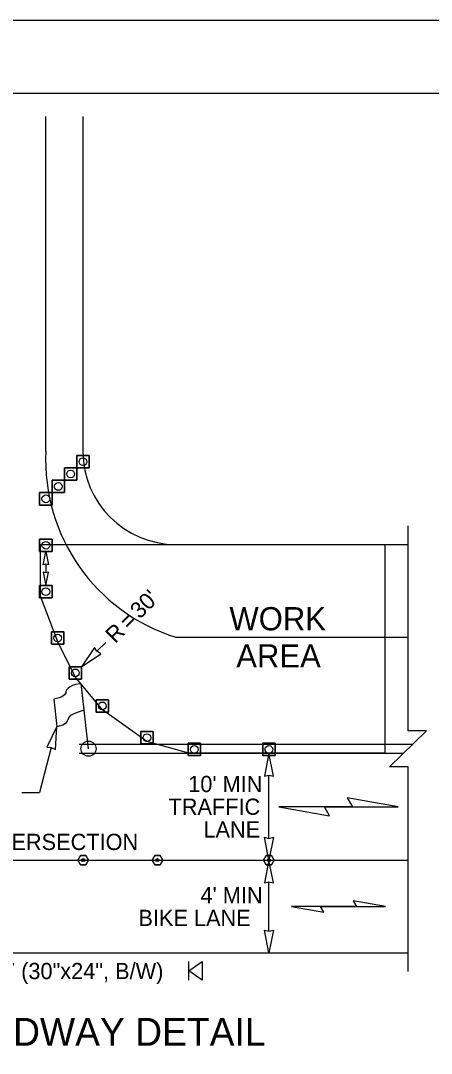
# Model space of a CAD drawing. Extents: x 99998.9 to 100095.7, y 99995 to 100010.7.
# Drawn here: x 100068.607 to 100070.375, y 100006.238 to 100010.687 of the extents above; entities that cross this region are included whole.
import ezdxf

# ---------------------------------------------------------------- set-up
doc = ezdxf.new("R2010")
doc.units = 0
for name, color, linetype in [('RD_ED_ShoulderPavedEdge', 7, 'Continuous'), ('RD_MK_LineDblYellowCenter', 7, 'Continuous'), ('RD_MK_LineEdgeWhite', 7, 'Continuous'), ('SH_DE_DetailHeading2Text', 7, 'Continuous'), ('SH_GI_PlotLimits', 7, 'Continuous'), ('SH_GI_SheetBorder', 7, 'Continuous'), ('TR_WZ_FlaggingStation', 7, 'Continuous'), ('TR_WZ_PortableSignMountBlk-Wht', 7, 'Continuous'), ('TR_WZ_TrafficCone', 7, 'Continuous'), ('TR_WZ_TubularMarker', 7, 'Continuous'), ('TR_WZ_WorkAreaLabel', 7, 'Continuous'), ('TR_WZ_WorkZoneDetails', 7, 'Continuous'), ('TR_WZ_WorkZoneTextCurrent', 7, 'Continuous')]:
    doc.layers.add(name, color=color, linetype=linetype)

msp = doc.modelspace()

# ---------------------------------------------------------------- linework, layer by layer
at = {"layer": 'RD_ED_ShoulderPavedEdge'}
for p, q in [((100069.275, 100008.4305), (100070.275, 100008.4305)), ((100065.475, 100006.6704), (100070.275, 100006.6704))]:
    msp.add_line(p, q, dxfattribs=at)
msp.add_lwpolyline([(100068.875, 100010.275), (100068.875, 100008.8304)], dxfattribs=at)
msp.add_arc((100069.275, 100008.8304), 0.4, 180, 270, dxfattribs=at)
at = {"layer": 'RD_MK_LineDblYellowCenter'}
for p, q in [((100068.8588, 100007.5704), (100070.2957, 100007.5704)), ((100068.8588, 100007.5305), (100070.2543, 100007.5305))]:
    msp.add_line(p, q, dxfattribs=at)
at = {"layer": 'RD_MK_LineEdgeWhite'}
for p, q in [((100068.715, 100008.8304), (100068.715, 100010.275)), ((100069.275, 100008.0305), (100070.275, 100008.0305)), ((100065.475, 100007.0704), (100070.275, 100007.0704))]:
    msp.add_line(p, q, dxfattribs=at)
msp.add_arc((100069.5142, 100008.7939), 0.8, 177.3788, 252.6052, dxfattribs=at)
at = {"layer": 'SH_GI_PlotLimits'}
msp.add_lwpolyline([(100059.0625, 99999.6875), (100076.0625, 99999.6875), (100076.0625, 100010.6875), (100059.0625, 100010.6875)], close=True, dxfattribs=at)
at = {"layer": 'SH_GI_SheetBorder'}
msp.add_line((100060, 100010.375), (100075.75, 100010.375), dxfattribs=at)
at = {"layer": 'TR_WZ_FlaggingStation'}
for p, q in [((100068.8797, 100007.7174), (100068.8667, 100007.8317)), ((100068.8988, 100007.5504), (100068.8667, 100007.8314)), ((100068.7487, 100007.7639), (100068.762, 100007.6467)), ((100068.8797, 100007.7174), (100068.8797, 100007.7174))]:
    msp.add_line(p, q, dxfattribs=at)
for points in [[(100068.8667, 100007.8317), (100068.8609, 100007.8304), (100068.8431, 100007.827), (100068.8293, 100007.8228), (100068.8196, 100007.8167), (100068.8111, 100007.812), (100068.8054, 100007.8052), (100068.8012, 100007.7973), (100068.8006, 100007.7912), (100068.7953, 100007.7819), (100068.7845, 100007.7745), (100068.7721, 100007.7693), (100068.7487, 100007.7639)], [(100068.762, 100007.6467), (100068.7702, 100007.6481), (100068.7879, 100007.6528), (100068.8035, 100007.6633), (100068.81, 100007.6738), (100068.814, 100007.6841), (100068.823, 100007.695), (100068.834, 100007.7012), (100068.8514, 100007.7083), (100068.8797, 100007.7174)]]:
    msp.add_lwpolyline(points, dxfattribs=at)
msp.add_circle((100068.8988, 100007.5504), 0.0325, dxfattribs=at)
at = {"layer": 'TR_WZ_PortableSignMountBlk-Wht'}
msp.add_line((100069.331, 100006.5536), (100069.331, 100006.6336), dxfattribs=at)
msp.add_lwpolyline([(100069.331, 100006.5935), (100069.3885, 100006.6336), (100069.3885, 100006.5536)], close=True, dxfattribs=at)
at = {"layer": 'TR_WZ_TrafficCone'}
for points in [[(100068.8483, 100008.8138), (100068.8483, 100008.7605), (100068.9016, 100008.7605), (100068.9016, 100008.8138), (100068.8483, 100008.8138)], [(100068.9016, 100008.8138), (100068.9016, 100008.7605), (100068.8483, 100008.7605), (100068.8483, 100008.8138), (100068.9016, 100008.8138)], [(100068.795, 100008.7605), (100068.795, 100008.7071), (100068.8483, 100008.7071), (100068.8483, 100008.7605), (100068.795, 100008.7605)], [(100068.8483, 100008.7605), (100068.8483, 100008.7071), (100068.795, 100008.7071), (100068.795, 100008.7605), (100068.8483, 100008.7605)], [(100068.7416, 100008.7071), (100068.7416, 100008.6538), (100068.795, 100008.6538), (100068.795, 100008.7071), (100068.7416, 100008.7071)], [(100068.795, 100008.7071), (100068.795, 100008.6538), (100068.7416, 100008.6538), (100068.7416, 100008.7071), (100068.795, 100008.7071)], [(100068.6883, 100008.6538), (100068.7416, 100008.6538), (100068.7416, 100008.6005), (100068.6883, 100008.6005), (100068.6883, 100008.6538)], [(100068.6883, 100008.6005), (100068.7416, 100008.6005), (100068.7416, 100008.6538), (100068.6883, 100008.6538), (100068.6883, 100008.6005)], [(100068.6883, 100008.4538), (100068.7416, 100008.4538), (100068.7416, 100008.4005), (100068.6883, 100008.4005), (100068.6883, 100008.4538)], [(100068.6883, 100008.4005), (100068.7416, 100008.4005), (100068.7416, 100008.4538), (100068.6883, 100008.4538), (100068.6883, 100008.4005)], [(100068.6883, 100008.2538), (100068.7416, 100008.2538), (100068.7416, 100008.2005), (100068.6883, 100008.2005), (100068.6883, 100008.2538)], [(100068.6883, 100008.2005), (100068.7416, 100008.2005), (100068.7416, 100008.2538), (100068.6883, 100008.2538), (100068.6883, 100008.2005)], [(100068.7393, 100008.0538), (100068.7927, 100008.0538), (100068.7927, 100008.0005), (100068.7393, 100008.0005), (100068.7393, 100008.0538)], [(100068.7393, 100008.0005), (100068.7927, 100008.0005), (100068.7927, 100008.0538), (100068.7393, 100008.0538), (100068.7393, 100008.0005)], [(100068.815, 100007.9038), (100068.8683, 100007.9038), (100068.8683, 100007.8505), (100068.815, 100007.8505), (100068.815, 100007.9038)], [(100068.815, 100007.8505), (100068.8683, 100007.8505), (100068.8683, 100007.9038), (100068.815, 100007.9038), (100068.815, 100007.8505)], [(100068.9319, 100007.7615), (100068.9853, 100007.7615), (100068.9853, 100007.7082), (100068.9319, 100007.7082), (100068.9319, 100007.7615)], [(100068.9319, 100007.7082), (100068.9853, 100007.7082), (100068.9853, 100007.7615), (100068.9319, 100007.7615), (100068.9319, 100007.7082)], [(100069.1236, 100007.6247), (100069.177, 100007.6247), (100069.177, 100007.5714), (100069.1236, 100007.5714), (100069.1236, 100007.6247)], [(100069.1236, 100007.5714), (100069.177, 100007.5714), (100069.177, 100007.6247), (100069.1236, 100007.6247), (100069.1236, 100007.5714)], [(100069.3276, 100007.5738), (100069.381, 100007.5738), (100069.381, 100007.5205), (100069.3276, 100007.5205), (100069.3276, 100007.5738)], [(100069.3276, 100007.5205), (100069.381, 100007.5205), (100069.381, 100007.5738), (100069.3276, 100007.5738), (100069.3276, 100007.5205)], [(100069.649, 100007.5738), (100069.7024, 100007.5738), (100069.7024, 100007.5205), (100069.649, 100007.5205), (100069.649, 100007.5738)], [(100069.649, 100007.5205), (100069.7024, 100007.5205), (100069.7024, 100007.5738), (100069.649, 100007.5738), (100069.649, 100007.5205)]]:
    msp.add_lwpolyline(points, dxfattribs=at)
for centre in [(100068.875, 100008.7871), (100068.8216, 100008.7338), (100068.7683, 100008.6805), (100068.715, 100008.6271), (100068.715, 100008.4271), (100068.715, 100008.2271), (100068.766, 100008.0271), (100068.8417, 100007.8771), (100068.9586, 100007.7349), (100069.1503, 100007.598), (100069.3543, 100007.5471), (100069.6757, 100007.5471)]:
    msp.add_circle(centre, 0.0167, dxfattribs=at)
at = {"layer": 'TR_WZ_TubularMarker'}
for points in [[(100068.8526, 100007.0704), (100068.8641, 100007.0904), (100068.8872, 100007.0904), (100068.8988, 100007.0704), (100068.8872, 100007.0504), (100068.8641, 100007.0504)], [(100069.1726, 100007.0704), (100069.1841, 100007.0904), (100069.2072, 100007.0904), (100069.2188, 100007.0704), (100069.2072, 100007.0504), (100069.1841, 100007.0504)], [(100069.6526, 100007.0704), (100069.6641, 100007.0904), (100069.6872, 100007.0904), (100069.6988, 100007.0704), (100069.6872, 100007.0504), (100069.6641, 100007.0504)]]:
    msp.add_lwpolyline(points, close=True, dxfattribs=at)
for points in [[(100068.8641, 100007.0504), (100068.8872, 100007.0504), (100068.8988, 100007.0704), (100068.8872, 100007.0904), (100068.8641, 100007.0904), (100068.8526, 100007.0704), (100068.8641, 100007.0504)], [(100069.1841, 100007.0504), (100069.2072, 100007.0504), (100069.2188, 100007.0704), (100069.2072, 100007.0904), (100069.1841, 100007.0904), (100069.1726, 100007.0704), (100069.1841, 100007.0504)], [(100069.6641, 100007.0504), (100069.6872, 100007.0504), (100069.6988, 100007.0704), (100069.6872, 100007.0904), (100069.6641, 100007.0904), (100069.6526, 100007.0704), (100069.6641, 100007.0504)]]:
    msp.add_lwpolyline(points, dxfattribs=at)
for centre in [(100068.8757, 100007.0704), (100069.1957, 100007.0704), (100069.6757, 100007.0704)]:
    msp.add_circle(centre, 0.00667, dxfattribs=at)
at = {"layer": 'TR_WZ_WorkZoneDetails'}
for p, q in [((100068.715, 100008.3459), (100068.715, 100008.3083)), ((100068.9346, 100007.9701), (100068.973, 100008.0085)), ((100068.7385, 100007.556), (100068.688, 100007.3613)), ((100069.6756, 100007.1642), (100069.6756, 100007.4367)), ((100068.6118, 100007.3613), (100068.688, 100007.3613)), ((100070.0356, 100007.3005), (100069.7945, 100007.3005)), ((100069.9151, 100007.3005), (100070.1562, 100007.3005)), ((100069.6756, 100006.7642), (100069.6756, 100006.9767)), ((100070.0525, 100006.8704), (100069.8982, 100006.8704)), ((100069.8982, 100006.8704), (100070.0525, 100006.8704))]:
    msp.add_line(p, q, dxfattribs=at)
msp.add_lwpolyline([(100070.275, 100006.5904), (100070.275, 100007.473), (100070.195, 100007.473), (100070.355, 100007.6279), (100070.275, 100007.6279), (100070.275, 100008.5105)], dxfattribs=at)
for points in [[(100070.175, 100008.4305), (100070.175, 100007.5305), (100069.699, 100007.5305), (100069.6523, 100007.5305), (100069.6523, 100007.5305), (100069.6523, 100007.5305), (100069.331, 100007.5305), (100069.331, 100007.5305), (100069.331, 100007.5305), (100069.1503, 100007.5814), (100068.9586, 100007.7182), (100068.8417, 100007.8605), (100068.766, 100008.0105), (100068.6917, 100008.2071), (100068.6917, 100008.4305)], [(100068.715, 100008.4005), (100068.7262, 100008.3433), (100068.715, 100008.3459), (100068.7037, 100008.3433)], [(100068.715, 100008.2538), (100068.7262, 100008.3109), (100068.715, 100008.3083), (100068.7038, 100008.3109)], [(100068.8683, 100007.9038), (100068.9514, 100007.9597), (100068.9346, 100007.9701), (100068.9242, 100007.987)], [(100068.762, 100007.6467), (100068.7187, 100007.5564), (100068.7385, 100007.556), (100068.7561, 100007.5467)], [(100069.6757, 100007.5305), (100069.6564, 100007.4322), (100069.6757, 100007.4367), (100069.695, 100007.4322)], [(100070.2321, 100007.3005), (100070.0133, 100007.339), (100070.0356, 100007.3005)], [(100069.7185, 100007.3005), (100069.9373, 100007.2619), (100069.9151, 100007.3005)], [(100069.6756, 100007.0704), (100069.6564, 100007.1687), (100069.6756, 100007.1642), (100069.6949, 100007.1687)], [(100069.6756, 100007.0704), (100069.6564, 100006.9722), (100069.6756, 100006.9767), (100069.6949, 100006.9722)], [(100070.1783, 100006.8704), (100070.0382, 100006.8951), (100070.0525, 100006.8704)], [(100069.7724, 100006.8704), (100069.9124, 100006.8458), (100069.8982, 100006.8704)], [(100069.6756, 100006.6704), (100069.6564, 100006.7687), (100069.6756, 100006.7642), (100069.6949, 100006.7687)]]:
    msp.add_lwpolyline(points, close=True, dxfattribs=at)

# ---------------------------------------------------------------- texts
at = {"layer": 'SH_DE_DetailHeading2Text'}
msp.add_text('UNSIGNALIZED INTERSECTING ROADWAY DETAIL', height=0.12, rotation=360, dxfattribs=at).set_placement((100065.7563, 100006.2704))
at = {"layer": 'TR_WZ_WorkAreaLabel'}
for s, p in [('WORK', (100069.5056, 100008.0605)), ('AREA', (100069.5352, 100007.9004))]:
    msp.add_text(s, height=0.1, dxfattribs=at).set_placement(p)
at = {"layer": 'TR_WZ_WorkZoneDetails'}
msp.add_text('R3-17 (30"x24", B/W)', height=0.07, rotation=360, dxfattribs=at).set_placement((100068.3277, 100006.5575))
at = {"layer": 'TR_WZ_WorkZoneTextCurrent'}
for s, p in [("30'", (100069.1202, 100008.1062)), ('=', (100069.0734, 100008.0593)), ('R', (100069.0142, 100008.0002))]:
    msp.add_text(s, height=0.07, rotation=45, dxfattribs=at).set_placement(p)
for s, p in [("10' MIN", (100069.3283, 100007.3635)), ('TRAFFIC', (100069.2433, 100007.2655)), ('LANE', (100069.3937, 100007.1675)), ("10' SPACING ACROSS INTERSECTION", (100067.3993, 100007.1138)), ("4' MIN", (100069.3812, 100006.8844)), ('BIKE LANE', (100069.1137, 100006.7864))]:
    msp.add_text(s, height=0.07, dxfattribs=at).set_placement(p)

doc.saveas('drawing.dxf')
